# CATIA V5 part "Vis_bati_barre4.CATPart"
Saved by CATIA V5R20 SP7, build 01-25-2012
Part number: Vis_bati_barre4
Bounding box of the stored display mesh (mm): x -7 to 0.5, y -0.996 to 0.996, z -0.996 to 0.996
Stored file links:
  J:\IFMA\IAO\système avant mef\Vis_bati_barre4.CATPart
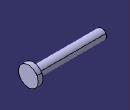
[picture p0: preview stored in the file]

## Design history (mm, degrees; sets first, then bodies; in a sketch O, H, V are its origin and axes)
Body1 (main body)
  Line1: stored without definition
  Line2 "axe_liaison_barre4_bati": stored without definition
  Line3 "axe_liaison_barre4_bati": stored without definition
  Point1 "Point_F_vis": stored without definition
  DatumCurve1
  Line4 "axe_liaison_barre4_bati": stored without definition
  Sketch1 on xy-plane, origin (0, 0, 0), H (1, 0, 0), V (0, 1, 0)
    line L1 (-7, -0.5) -> (0, -0.5)
    line L2 (0, -0.5) -> (0, -1)
    line L3 (0, -1) -> (0.5, -1)
    reference projected line E1 (0, 0) -> (20, 0) from Line3
    reference projected line E2 (0, 2.2748) -> (0, -0.8903) from edge of DatumCurve1
    line L4 (-7, -0.5) -> (-7, 0)
    point P5 (-7, 0)
    line L5 (0.5, -1) -> (0.5, 0)
    point P6 (0.5, 0)
    distance L3 E1 = 1
    horizontal: L1 H, L3 H
    vertical: L2 V, L4 V, L5 V
    coincidence: L2 E2, P5 H, P6 H
  Shaft1: profile Sketch1, axis Line4, angle 360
